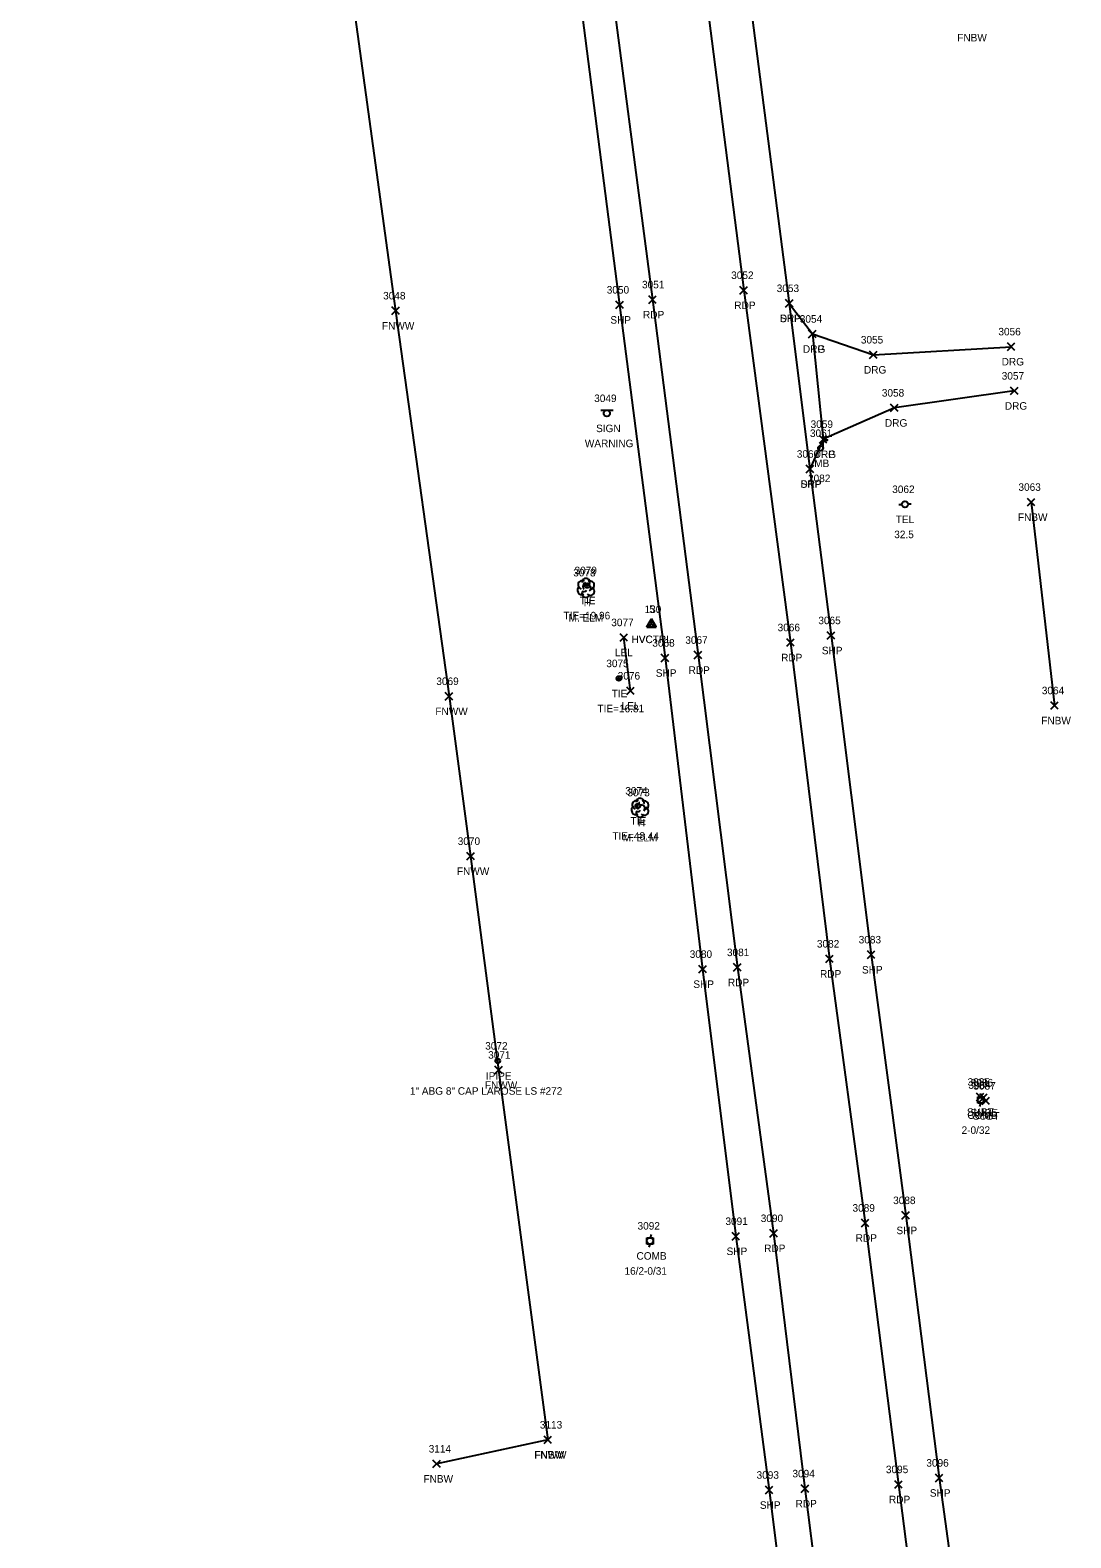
# Model space of a CAD drawing. Extents: x 1443071 to 1445292, y 614024 to 622563.
# Drawn here: x 1444083.9 to 1444360.8, y 617213.4 to 617614.4 of the extents above; entities that cross this region are included whole.
import ezdxf

# ---------------------------------------------------------------- set-up
doc = ezdxf.new("R2010")
doc.units = 0
for name, color, linetype in [('C_A', 7, 'Continuous'), ('C_C', 7, 'Continuous'), ('C_I', 7, 'Continuous'), ('CBP', 7, 'Continuous'), ('CPSM', 7, 'Continuous'), ('L_A', 7, 'Continuous'), ('L_C', 7, 'Continuous'), ('L_I', 7, 'Continuous'), ('L_TIC', 7, 'Continuous'), ('LARO', 7, 'Continuous'), ('LFNC', 7, 'Continuous'), ('LMB', 7, 'Continuous'), ('LTD', 7, 'Continuous'), ('M_A', 7, 'Continuous'), ('M_C', 7, 'Continuous'), ('M_I', 7, 'Continuous'), ('MPIP', 7, 'Continuous'), ('P_A', 7, 'Continuous'), ('P_I', 7, 'Continuous'), ('P_TIC', 7, 'Continuous'), ('PET', 7, 'Continuous'), ('PSP', 7, 'Continuous'), ('R_A', 7, 'Continuous'), ('R_I', 7, 'Continuous'), ('R_TIC', 7, 'Continuous'), ('RDG', 7, 'Continuous'), ('RDP', 7, 'Continuous'), ('S_A', 7, 'Continuous'), ('S_C', 7, 'Continuous'), ('S_I', 7, 'Continuous'), ('SSGN', 7, 'Continuous'), ('U_A', 7, 'Continuous'), ('U_C', 7, 'Continuous'), ('U_I', 7, 'Continuous'), ('U_TIC', 7, 'Continuous'), ('UP', 7, 'Continuous')]:
    doc.layers.add(name, color=color, linetype=linetype)

msp = doc.modelspace()

# ---------------------------------------------------------------- linework, layer by layer
at = {"layer": 'CBP'}
for centre, radius in [((1444232.08, 617466.68), 0.625), ((1444232.08, 617466.68), 0.0833), ((1444240.53, 617441.96), 0.625), ((1444240.53, 617441.96), 0.0833), ((1444245.56, 617408.07), 0.625), ((1444245.56, 617408.07), 0.0833)]:
    msp.add_circle(centre, radius, dxfattribs=at)
at = {"layer": 'CPSM'}
for p, q in [((1444247.93, 617455.65), (1444249.18, 617457.82)), ((1444247.99, 617455.64), (1444249.24, 617457.81)), ((1444250.43, 617455.65), (1444249.18, 617457.82)), ((1444249.18, 617456.38), (1444249.18, 617457.82)), ((1444250.49, 617455.64), (1444249.24, 617457.81)), ((1444249.24, 617456.36), (1444249.24, 617457.81)), ((1444247.93, 617455.65), (1444249.18, 617456.38)), ((1444247.93, 617455.65), (1444250.43, 617455.65)), ((1444247.99, 617455.64), (1444249.24, 617456.36)), ((1444247.99, 617455.64), (1444250.49, 617455.64)), ((1444249.18, 617456.38), (1444249.18, 617456.38)), ((1444249.18, 617456.38), (1444250.43, 617455.65)), ((1444249.24, 617456.36), (1444249.24, 617456.36)), ((1444249.24, 617456.36), (1444250.49, 617455.64))]:
    msp.add_line(p, q, dxfattribs=at)
at = {"layer": 'L_TIC'}
for points in [[(1444180.16, 617538.76), (1444182.16, 617540.76)], [(1444182.16, 617538.76), (1444180.16, 617540.76)], [(1444349.21, 617487.86), (1444351.21, 617489.86)], [(1444351.21, 617487.86), (1444349.21, 617489.86)], [(1444240.85, 617451.86), (1444242.85, 617453.86)], [(1444242.85, 617451.86), (1444240.85, 617453.86)], [(1444194.37, 617436.22), (1444196.37, 617438.22)], [(1444196.37, 617436.22), (1444194.37, 617438.22)], [(1444242.62, 617437.66), (1444244.62, 617439.66)], [(1444244.62, 617437.66), (1444242.62, 617439.66)], [(1444355.42, 617433.76), (1444357.42, 617435.76)], [(1444357.42, 617433.76), (1444355.42, 617435.76)], [(1444200.1, 617393.69), (1444202.1, 617395.69)], [(1444202.1, 617393.69), (1444200.1, 617395.69)], [(1444207.54, 617336.83), (1444209.54, 617338.83)], [(1444209.54, 617336.83), (1444207.54, 617338.83)], [(1444220.64, 617238.47), (1444222.64, 617240.47)], [(1444222.64, 617238.47), (1444220.64, 617240.47)], [(1444220.64, 617238.47), (1444222.64, 617240.47)], [(1444222.64, 617238.47), (1444220.64, 617240.47)], [(1444191.08, 617232.09), (1444193.08, 617234.09)], [(1444193.08, 617232.09), (1444191.08, 617234.09)]]:
    msp.add_lwpolyline(points, dxfattribs=at)
at = {"layer": 'LARO'}
msp.add_lwpolyline([(1444243.62, 617438.66), (1444241.85, 617452.86)], dxfattribs=at)
at = {"layer": 'LFNC'}
for points in [[(1444083.93, 618296.19), (1444095.32, 618214.33), (1444111.27, 618081.76), (1444124.56, 617981.26), (1444135.13, 617897.63), (1444146.03, 617811.43), (1444159.7, 617705.33), (1444169.41, 617624.98), (1444181.16, 617539.76), (1444195.37, 617437.22), (1444201.1, 617394.69), (1444208.54, 617337.83), (1444221.64, 617239.47)], [(1444350.21, 617488.86), (1444356.42, 617434.76)], [(1444221.64, 617239.47), (1444192.08, 617233.09)]]:
    msp.add_lwpolyline(points, dxfattribs=at)
at = {"layer": 'LMB'}
for p, q in [((1444294.83, 617505.78), (1444296.13, 617505.4)), ((1444294.84, 617503.19), (1444294.84, 617505.79)), ((1444294.84, 617504.88), (1444296.12, 617505.39)), ((1444294.18, 617503.18), (1444294.18, 617503.18))]:
    msp.add_line(p, q, dxfattribs=at)
msp.add_circle((1444294.18, 617503.18), 0.656, dxfattribs=at)
at = {"layer": 'LTD'}
for p, q in [((1444231.74, 617466.1), (1444231.74, 617466.1)), ((1444231.74, 617466.1), (1444231.74, 617466.1)), ((1444246.13, 617407.62), (1444246.13, 617407.62)), ((1444246.13, 617407.62), (1444246.13, 617407.62))]:
    msp.add_line(p, q, dxfattribs=at)
for centre in [(1444231.79, 617467.53), (1444246.18, 617409.05)]:
    msp.add_arc(centre, 1.05, 335.5272, 180.9563, dxfattribs=at)
for centre, major_axis, ratio, start_param, end_param in [((1444230.66, 617465.39), (0.58, -1.04), 0.959034, 3.141593, 6.283185), ((1444230.95, 617466.77), (1.21, -0.51), 0.895232, 1.570796, 4.712389), ((1444231.28, 617465.35), (-0.625, -0.083), 0.423636, 0, 3.141593), ((1444231.53, 617466.56), (-0.208, -0.792), 0.645439, 3.141593, 6.283185), ((1444232.24, 617465.93), (-0.5, 0.667), 0.989748, 3.141593, 6.283185), ((1444232.74, 617465.27), (-1.09, 0.79), 0.841452, 1.570796, 4.712389), ((1444232.78, 617466.68), (-1.14, -0.48), 0.949671, 1.570796, 4.712389), ((1444231.74, 617464.6), (0.26, 1.06), 0.942809, 1.570796, 4.712389), ((1444245.34, 617408.28), (1.21, -0.51), 0.895232, 1.570796, 4.712389), ((1444245.93, 617408.08), (-0.208, -0.792), 0.645439, 3.141593, 6.283185), ((1444247.18, 617408.2), (-1.14, -0.48), 0.949671, 1.570796, 4.712389), ((1444245.05, 617406.91), (0.58, -1.04), 0.959034, 3.141593, 6.283185), ((1444246.13, 617406.12), (0.26, 1.06), 0.942809, 1.570796, 4.712389), ((1444245.68, 617406.87), (-0.625, -0.083), 0.423636, 0, 3.141593), ((1444246.63, 617407.45), (-0.5, 0.667), 0.989748, 3.141593, 6.283185), ((1444247.13, 617406.78), (-1.09, 0.79), 0.841452, 1.570796, 4.712389)]:
    msp.add_ellipse(centre, major_axis=major_axis, ratio=ratio, start_param=start_param, end_param=end_param, dxfattribs=at)
at = {"layer": 'MPIP'}
for radius in [0.625, 0.0833]:
    msp.add_circle((1444208.32, 617340.25), radius, dxfattribs=at)
at = {"layer": 'P_TIC'}
for points in [[(1444272.75, 617544.2), (1444274.75, 617546.2)], [(1444274.75, 617544.2), (1444272.75, 617546.2)], [(1444239.73, 617540.32), (1444241.73, 617542.32)], [(1444241.73, 617540.32), (1444239.73, 617542.32)], [(1444248.46, 617541.71), (1444250.46, 617543.71)], [(1444250.46, 617541.71), (1444248.46, 617543.71)], [(1444284.85, 617540.72), (1444286.85, 617542.72)], [(1444286.85, 617540.72), (1444284.85, 617542.72)], [(1444290.35, 617496.66), (1444292.35, 617498.66)], [(1444292.35, 617496.66), (1444290.35, 617498.66)], [(1444295.98, 617452.39), (1444297.98, 617454.39)], [(1444297.98, 617452.39), (1444295.98, 617454.39)], [(1444260.59, 617447.18), (1444262.59, 617449.18)], [(1444262.59, 617447.18), (1444260.59, 617449.18)], [(1444285.2, 617450.52), (1444287.2, 617452.52)], [(1444287.2, 617450.52), (1444285.2, 617452.52)], [(1444251.82, 617446.41), (1444253.82, 617448.41)], [(1444253.82, 617446.41), (1444251.82, 617448.41)], [(1444306.66, 617367.49), (1444308.66, 617369.49)], [(1444308.66, 617367.49), (1444306.66, 617369.49)], [(1444261.81, 617363.65), (1444263.81, 617365.65)], [(1444263.81, 617363.65), (1444261.81, 617365.65)], [(1444271.05, 617364.11), (1444273.05, 617366.11)], [(1444273.05, 617364.11), (1444271.05, 617366.11)], [(1444295.55, 617366.39), (1444297.55, 617368.39)], [(1444297.55, 617366.39), (1444295.55, 617368.39)], [(1444305.03, 617296.15), (1444307.03, 617298.15)], [(1444307.03, 617296.15), (1444305.03, 617298.15)], [(1444315.83, 617298.16), (1444317.83, 617300.16)], [(1444317.83, 617298.16), (1444315.83, 617300.16)], [(1444270.65, 617292.61), (1444272.65, 617294.61)], [(1444272.65, 617292.61), (1444270.65, 617294.61)], [(1444280.69, 617293.39), (1444282.69, 617295.39)], [(1444282.69, 617293.39), (1444280.69, 617295.39)], [(1444313.9, 617226.6), (1444315.9, 617228.6)], [(1444315.9, 617226.6), (1444313.9, 617228.6)], [(1444324.72, 617228.34), (1444326.72, 617230.34)], [(1444326.72, 617228.34), (1444324.72, 617230.34)], [(1444279.5, 617225.12), (1444281.5, 617227.12)], [(1444281.5, 617225.12), (1444279.5, 617227.12)], [(1444289.04, 617225.49), (1444291.04, 617227.49)], [(1444291.04, 617225.49), (1444289.04, 617227.49)]]:
    msp.add_lwpolyline(points, dxfattribs=at)
at = {"layer": 'PET'}
for points in [[(1444109.49, 618620.85), (1444119.47, 618545.62), (1444130.61, 618455.68), (1444144.21, 618352.46), (1444156.88, 618257.4), (1444168.48, 618168.47), (1444177.52, 618096.27), (1444190.69, 617993.23), (1444202, 617907.6), (1444212.88, 617824.23), (1444226.02, 617721.24), (1444236.79, 617639.47), (1444249.46, 617542.71), (1444261.59, 617448.18), (1444272.05, 617365.11), (1444281.69, 617294.39), (1444290.04, 617226.49), (1444293.29, 617200.68)], [(1444134.15, 618623.05), (1444144.16, 618546.64), (1444155.44, 618457.71), (1444168.74, 618355.37), (1444181.06, 618259.94), (1444192.98, 618171.23), (1444202.29, 618096.22), (1444214.98, 617996.62), (1444226.22, 617910.85), (1444236.58, 617828.89), (1444250.39, 617724.54), (1444261.29, 617642.54), (1444273.75, 617545.2), (1444286.2, 617451.52), (1444296.55, 617367.39), (1444306.03, 617297.15), (1444314.9, 617227.6), (1444331.28, 617099.37)]]:
    msp.add_lwpolyline(points, dxfattribs=at)
at = {"layer": 'PSP'}
for points in [[(1444144.78, 618624.26), (1444154.69, 618549.98), (1444166.36, 618458.69), (1444180.45, 618353.82), (1444192.35, 618260.76), (1444204.1, 618173.53), (1444213.61, 618097.19), (1444225.79, 617998.93), (1444236.89, 617912.38), (1444247.43, 617831.06), (1444261.19, 617727.11), (1444272.44, 617645.23), (1444285.85, 617541.72), (1444291.35, 617497.66), (1444296.98, 617453.39), (1444307.66, 617368.49), (1444316.83, 617299.16), (1444325.72, 617229.34), (1444331.18, 617190.03)], [(1444101.61, 618620.44), (1444111.35, 618544.8), (1444122.98, 618455.4), (1444136.42, 618350.98), (1444148.78, 618256.45), (1444160.51, 618166.98), (1444169.64, 618095.48), (1444183.2, 617992.65), (1444194.59, 617906.27), (1444205.17, 617824.27), (1444218.33, 617719.51), (1444228.19, 617638.49), (1444240.73, 617541.32), (1444252.82, 617447.41), (1444262.81, 617364.65), (1444271.65, 617293.61), (1444280.5, 617226.12), (1444283.66, 617200.61)]]:
    msp.add_lwpolyline(points, dxfattribs=at)
at = {"layer": 'R_TIC'}
for points in [[(1444284.85, 617540.72), (1444286.85, 617542.72)], [(1444286.85, 617540.72), (1444284.85, 617542.72)], [(1444291, 617532.58), (1444293, 617534.58)], [(1444293, 617532.58), (1444291, 617534.58)], [(1444291, 617532.58), (1444293, 617534.58)], [(1444293, 617532.58), (1444291, 617534.58)], [(1444307.24, 617527.04), (1444309.24, 617529.04)], [(1444309.24, 617527.04), (1444307.24, 617529.04)], [(1444343.87, 617529.2), (1444345.87, 617531.2)], [(1444345.87, 617529.2), (1444343.87, 617531.2)], [(1444344.71, 617517.44), (1444346.71, 617519.44)], [(1444346.71, 617517.44), (1444344.71, 617519.44)], [(1444312.82, 617512.92), (1444314.82, 617514.92)], [(1444314.82, 617512.92), (1444312.82, 617514.92)], [(1444293.87, 617504.58), (1444295.87, 617506.58)], [(1444295.87, 617504.58), (1444293.87, 617506.58)], [(1444293.87, 617504.58), (1444295.87, 617506.58)], [(1444295.87, 617504.58), (1444293.87, 617506.58)], [(1444290.35, 617496.66), (1444292.35, 617498.66)], [(1444292.35, 617496.66), (1444290.35, 617498.66)]]:
    msp.add_lwpolyline(points, dxfattribs=at)
at = {"layer": 'RDG'}
for points in [[(1444292, 617533.58), (1444308.24, 617528.04), (1444344.87, 617530.2)], [(1444345.71, 617518.44), (1444313.82, 617513.92), (1444294.87, 617505.58)]]:
    msp.add_lwpolyline(points, dxfattribs=at)
at = {"layer": 'RDP'}
msp.add_lwpolyline([(1444285.85, 617541.72), (1444292, 617533.58), (1444294.87, 617505.58), (1444291.35, 617497.66)], dxfattribs=at)
at = {"layer": 'SSGN'}
for p, q in [((1444235.69, 617513.33), (1444239.02, 617513.33)), ((1444237.33, 617512.49), (1444237.33, 617512.49))]:
    msp.add_line(p, q, dxfattribs=at)
msp.add_circle((1444237.33, 617512.49), 0.833, dxfattribs=at)
at = {"layer": 'U_TIC'}
for points in [[(1444335.62, 617329.64), (1444337.62, 617331.64)], [(1444337.62, 617329.64), (1444335.62, 617331.64)], [(1444336.53, 617329.46), (1444338.53, 617331.46)], [(1444338.53, 617329.46), (1444336.53, 617331.46)], [(1444337.15, 617328.62), (1444339.15, 617330.62)], [(1444339.15, 617328.62), (1444337.15, 617330.62)]]:
    msp.add_lwpolyline(points, dxfattribs=at)
at = {"layer": 'UP'}
for p, q in [((1444314.97, 617488.26), (1444315.79, 617488.26)), ((1444316.63, 617488.27), (1444316.63, 617488.27)), ((1444318.29, 617488.27), (1444317.46, 617488.27)), ((1444317.46, 617488.27), (1444317.46, 617488.27)), ((1444318.29, 617488.27), (1444318.29, 617488.27)), ((1444335.99, 617329), (1444335.99, 617330.66)), ((1444335.99, 617330.66), (1444337.65, 617330.66)), ((1444337.65, 617329), (1444335.99, 617329)), ((1444336.57, 617328.16), (1444336.82, 617329)), ((1444337.07, 617331.5), (1444336.82, 617330.66)), ((1444336.82, 617329.83), (1444336.82, 617329.83)), ((1444337.65, 617330.66), (1444337.65, 617329)), ((1444248, 617291.54), (1444248, 617293.21)), ((1444248, 617293.21), (1444249.67, 617293.21)), ((1444249.08, 617294.04), (1444248.83, 617293.21)), ((1444249.67, 617293.21), (1444249.67, 617291.54)), ((1444249.67, 617291.54), (1444248, 617291.54)), ((1444248.58, 617290.71), (1444248.83, 617291.54)), ((1444248.83, 617292.38), (1444248.83, 617292.38))]:
    msp.add_line(p, q, dxfattribs=at)
for centre in [(1444316.63, 617488.27), (1444336.82, 617329.83), (1444248.83, 617292.38)]:
    msp.add_circle(centre, 0.833, dxfattribs=at)

# ---------------------------------------------------------------- texts
at = {"layer": 'C_A'}
for s, p in [('TIE', (1444230.16, 617461.68)), ('HVCTRL', (1444243.87, 617451.38)), ('HVCTRL', (1444243.93, 617451.36)), ('TIE', (1444238.61, 617436.96)), ('TIE', (1444243.64, 617403.07))]:
    msp.add_text(s, height=2, dxfattribs=at).set_placement(p)
at = {"layer": 'C_C'}
for s, p in [('TIE=19.96', (1444225.82, 617457.68)), ('TIE=16.81', (1444234.84, 617432.96)), ('TIE=48.44', (1444238.79, 617399.07))]:
    msp.add_text(s, height=2, dxfattribs=at).set_placement(p)
at = {"layer": 'C_I'}
for s, p in [('3079', (1444228.74, 617469.68)), ('130', (1444247.36, 617459.36)), ('5', (1444248.61, 617459.38)), ('3075', (1444237.19, 617444.96)), ('3074', (1444242.23, 617411.07))]:
    msp.add_text(s, height=2, dxfattribs=at).set_placement(p)
at = {"layer": 'L_A'}
for s, p in [('FNBW', (1444330.54, 617611.38)), ('FNWW', (1444177.51, 617534.76)), ('MB', (1444292.49, 617498.18)), ('FNBW', (1444346.68, 617483.86)), ('H', (1444231.17, 617461.1)), ('LEL', (1444239.48, 617447.86)), ('FNWW', (1444191.72, 617432.22)), ('LEL', (1444241.26, 617433.66)), ('FNBW', (1444352.89, 617429.76)), ('H', (1444245.57, 617402.62)), ('FNWW', (1444197.45, 617389.69)), ('FNWW', (1444204.89, 617332.83)), ('FNWW', (1444217.99, 617234.47)), ('FNBW', (1444218.11, 617234.47)), ('FNBW', (1444188.55, 617228.09))]:
    msp.add_text(s, height=2, dxfattribs=at).set_placement(p)
at = {"layer": 'L_C'}
for s, p in [('2082', (1444290.84, 617494.18)), ('M. ELM', (1444227.16, 617457.1)), ('M. ELM', (1444241.55, 617398.62))]:
    msp.add_text(s, height=2, dxfattribs=at).set_placement(p)
at = {"layer": 'L_I'}
for s, p in [('3048', (1444177.83, 617542.76)), ('3061', (1444291.36, 617506.18)), ('3063', (1444346.82, 617491.86)), ('3078', (1444228.4, 617469.1)), ('3077', (1444238.51, 617455.86)), ('3069', (1444191.98, 617440.22)), ('3076', (1444240.23, 617441.66)), ('3064', (1444353.03, 617437.76)), ('3073', (1444242.8, 617410.62)), ('3070', (1444197.67, 617397.69)), ('3071', (1444205.77, 617340.83)), ('3113', (1444219.52, 617242.47)), ('3113', (1444219.52, 617242.47)), ('3114', (1444189.95, 617236.09))]:
    msp.add_text(s, height=2, dxfattribs=at).set_placement(p)
at = {"layer": 'M_A'}
msp.add_text('IPIPE', height=2, dxfattribs=at).set_placement((1444205.16, 617335.25))
at = {"layer": 'M_C'}
msp.add_text('1" ABG 8" CAP LAROSE LS #272', height=2, dxfattribs=at).set_placement((1444184.94, 617331.25))
at = {"layer": 'M_I'}
msp.add_text('3072', height=2, dxfattribs=at).set_placement((1444204.98, 617343.25))
at = {"layer": 'P_A'}
for s, p in [('RDP', (1444271.24, 617540.2)), ('SHP', (1444238.27, 617536.32)), ('RDP', (1444246.95, 617537.71)), ('SHP', (1444283.39, 617536.72)), ('SHP', (1444288.88, 617492.66)), ('SHP', (1444294.52, 617448.39)), ('RDP', (1444259.07, 617443.18)), ('RDP', (1444283.69, 617446.52)), ('SHP', (1444250.35, 617442.41)), ('SHP', (1444305.2, 617363.49)), ('SHP', (1444260.34, 617359.65)), ('RDP', (1444269.54, 617360.11)), ('RDP', (1444294.04, 617362.39)), ('RDP', (1444303.52, 617292.15)), ('SHP', (1444314.37, 617294.16)), ('SHP', (1444269.19, 617288.61)), ('RDP', (1444279.18, 617289.39)), ('RDP', (1444312.38, 617222.6)), ('SHP', (1444323.25, 617224.34)), ('SHP', (1444278.04, 617221.12)), ('RDP', (1444287.53, 617221.49))]:
    msp.add_text(s, height=2, dxfattribs=at).set_placement(p)
at = {"layer": 'P_I'}
for s, p in [('3052', (1444270.41, 617548.2)), ('3050', (1444237.31, 617544.32)), ('3051', (1444246.69, 617545.71)), ('3053', (1444282.52, 617544.72)), ('3060', (1444287.87, 617500.66)), ('3065', (1444293.59, 617456.39)), ('3067', (1444258.2, 617451.18)), ('3066', (1444282.76, 617454.52)), ('3068', (1444249.43, 617450.41)), ('3083', (1444304.32, 617371.49)), ('3080', (1444259.38, 617367.65)), ('3081', (1444269.28, 617368.11)), ('3082', (1444293.21, 617370.39)), ('3089', (1444302.68, 617300.15)), ('3088', (1444313.49, 617302.16)), ('3091', (1444268.88, 617296.61)), ('3090', (1444278.27, 617297.39)), ('3095', (1444311.56, 617230.6)), ('3096', (1444322.32, 617232.34)), ('3093', (1444277.16, 617229.12)), ('3094', (1444286.7, 617229.49))]:
    msp.add_text(s, height=2, dxfattribs=at).set_placement(p)
at = {"layer": 'R_A'}
for s, p in [('DRP', (1444283.34, 617536.72)), ('DRG', (1444289.49, 617528.58)), ('DRP', (1444289.49, 617528.58)), ('DRG', (1444305.73, 617523.04)), ('DRG', (1444342.36, 617525.2)), ('DRG', (1444343.2, 617513.44)), ('DRG', (1444311.31, 617508.92)), ('DRG', (1444292.36, 617500.58)), ('DRP', (1444292.36, 617500.58)), ('DRP', (1444288.83, 617492.66))]:
    msp.add_text(s, height=2, dxfattribs=at).set_placement(p)
at = {"layer": 'R_I'}
for s, p in [('3053', (1444282.52, 617544.72)), ('3054', (1444288.66, 617536.58)), ('3054', (1444288.66, 617536.58)), ('3055', (1444304.9, 617531.04)), ('3056', (1444341.48, 617533.2)), ('3057', (1444342.37, 617521.44)), ('3058', (1444310.48, 617516.92)), ('3059', (1444291.53, 617508.58)), ('3059', (1444291.53, 617508.58)), ('3060', (1444287.87, 617500.66))]:
    msp.add_text(s, height=2, dxfattribs=at).set_placement(p)
at = {"layer": 'S_A'}
msp.add_text('SIGN', height=2, dxfattribs=at).set_placement((1444234.47, 617507.47))
at = {"layer": 'S_C'}
msp.add_text('WARNING', height=2, dxfattribs=at).set_placement((1444231.48, 617503.47))
at = {"layer": 'S_I'}
msp.add_text('3049', height=2, dxfattribs=at).set_placement((1444233.97, 617515.47))
at = {"layer": 'U_A'}
for s, p in [('TEL', (1444314.19, 617483.27)), ('SUBT', (1444333.12, 617325.64)), ('COMB', (1444333.21, 617324.83)), ('SUBE', (1444334.06, 617325.46)), ('SUBT', (1444334.65, 617324.62)), ('COMB', (1444245.22, 617287.38))]:
    msp.add_text(s, height=2, dxfattribs=at).set_placement(p)
at = {"layer": 'U_C'}
for s, p in [('32.5', (1444313.78, 617479.27)), ('2-0/32', (1444331.69, 617320.83)), ('16/2-0/31', (1444242.02, 617283.38))]:
    msp.add_text(s, height=2, dxfattribs=at).set_placement(p)
at = {"layer": 'U_I'}
for s, p in [('3062', (1444313.24, 617491.27)), ('3085', (1444333.28, 617333.64)), ('3084', (1444333.48, 617332.83)), ('3086', (1444334.13, 617333.46)), ('3087', (1444334.81, 617332.62)), ('3092', (1444245.5, 617295.38))]:
    msp.add_text(s, height=2, dxfattribs=at).set_placement(p)

doc.saveas('drawing.dxf')
